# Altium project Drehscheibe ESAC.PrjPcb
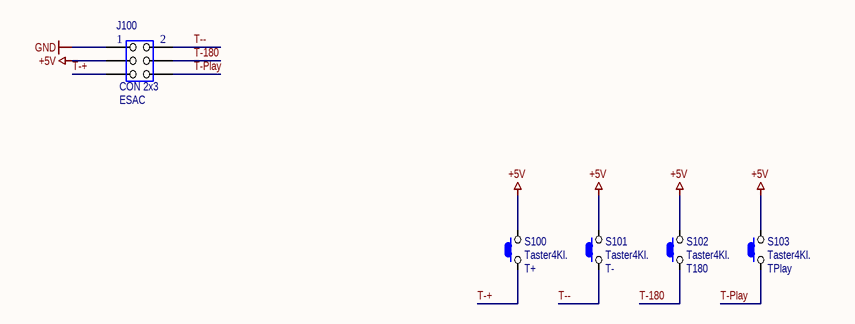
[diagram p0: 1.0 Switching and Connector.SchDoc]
City: Neustift-Innermanzing; Client: Wolfgang Paris, Gerhard Abraham; Company: PCSG; Country: Austria; Drawnby1: BRAL; Drawnby2: SONP; Email: office@pcsg.at; License: N/A; Number: 1; Phone: 02774/29452; Street: Hauptstraße 47; Title: Drehscheibe ESAC; Version: v1.0; Web: www.pcsg.at; ZIP: A-3052
1 sheet, 5 parts. Net scope: global (net labels, ports and power ports of the same name join across sheets).
Board file: PCB1.PcbDoc

## Sheet 1.0 Switching and Connector.SchDoc: Drehscheibe ESAC
size A4; SheetNumber: 1; SheetTotal: 1

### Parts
J100  CON 2x3  Use: ESAC  [J_2x3]
S100  Taster4Kl.  Use: T+  [S_THT_TasterKomb.]
S101  Taster4Kl.  Use: T-  [S_THT_TasterKomb.]
S102  Taster4Kl.  Use: T180  [S_THT_TasterKomb.]
S103  Taster4Kl.  Use: TPlay  [S_THT_TasterKomb.]

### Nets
+5V: J100.3 S100.2 S101.2 S102.2 S103.2
GND: J100.1
T-180: J100.4 S102.1
T-+: J100.5 S100.1
T--: J100.2 S101.1
T-Play: J100.6 S103.1

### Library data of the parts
J100 = J_THT_IDC 2x3: Stecker
S100-S103 = S_THT_Taster: Taster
